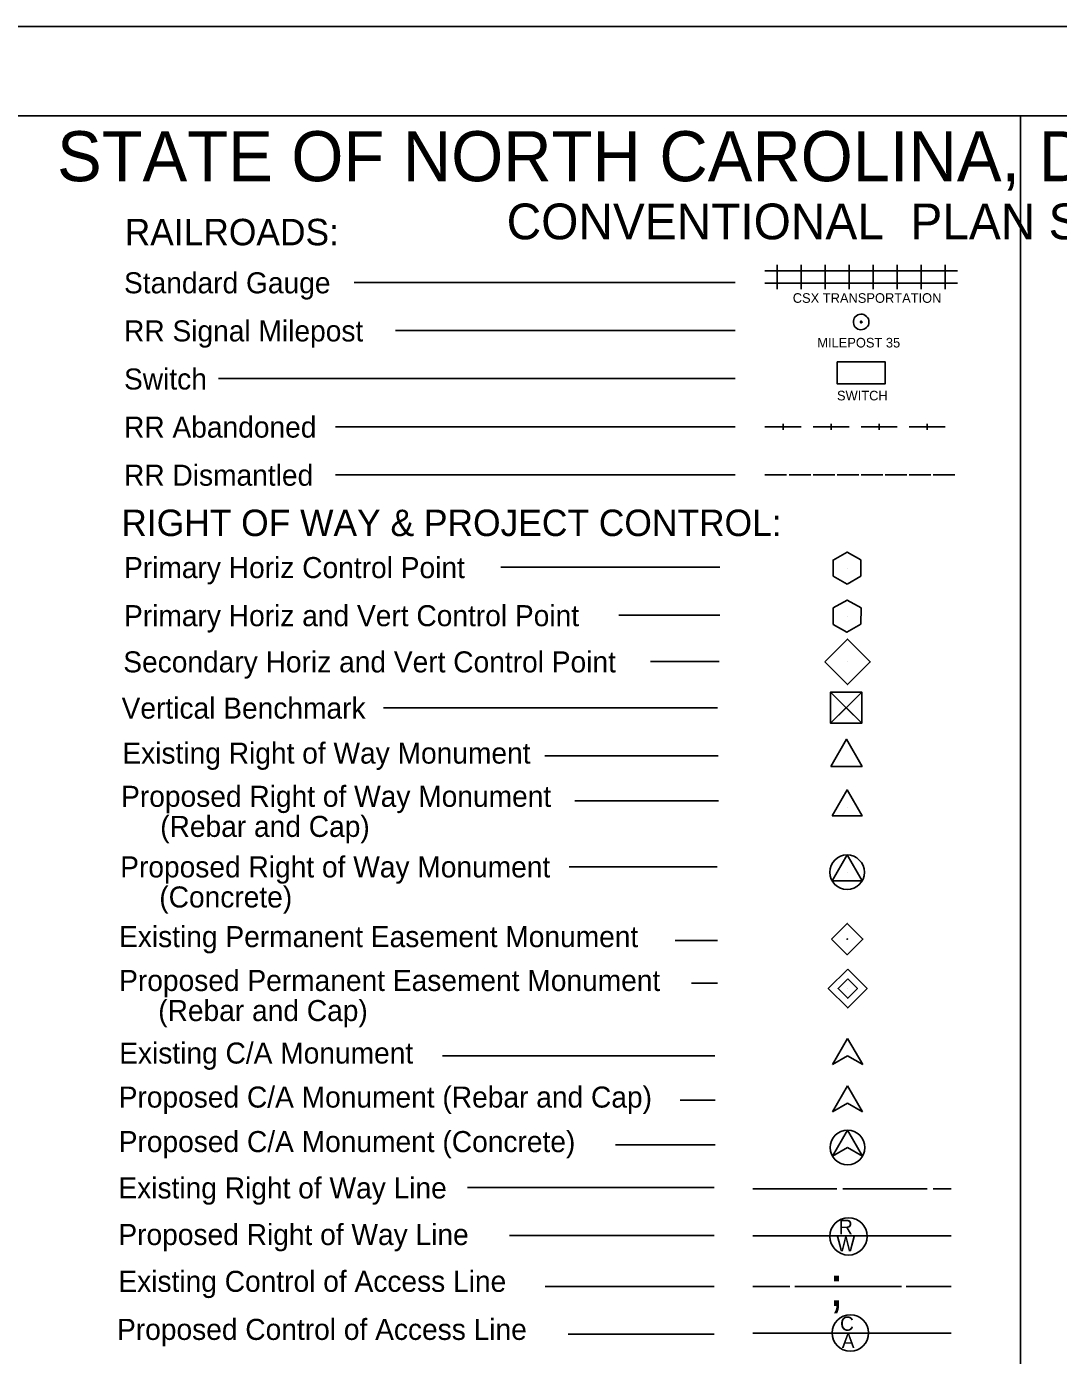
# Model space of a CAD drawing. Extents: x 0 to 3, y 0 to 1.83.
# Drawn here: x 0.722 to 1.443, y 0.904 to 1.833 of the extents above; entities that cross this region are included whole.
import ezdxf

# ---------------------------------------------------------------- set-up
doc = ezdxf.new("R2010")
doc.units = 0
for name, color, linetype in [('P_RDY_ROW_Permanent_Easement', 7, 'Continuous'), ('Sheet_Plan', 7, 'Continuous'), ('Sheet_Symbology', 7, 'Continuous'), ('z - Construction', 7, 'Continuous')]:
    doc.layers.add(name, color=color, linetype=linetype)

msp = doc.modelspace()

# ---------------------------------------------------------------- linework, layer by layer
at = {"layer": 'P_RDY_ROW_Permanent_Easement'}
msp.add_line((1.2958, 1.16066), (1.2958, 1.16066), dxfattribs=at)
for points in [[(1.2958, 1.1742), (1.30934, 1.16066), (1.2958, 1.14712), (1.28226, 1.16066)], [(1.2958, 1.16743), (1.30257, 1.16066), (1.2958, 1.15389), (1.28903, 1.16066)]]:
    msp.add_lwpolyline(points, close=True, dxfattribs=at)
at = {"layer": 'Sheet_Plan'}
msp.add_line((2.77083, 1.77083), (0.06249, 1.77083), dxfattribs=at)
at = {"layer": 'Sheet_Symbology'}
for p, q in [((1.24637, 1.64982), (1.24637, 1.66664)), ((1.26318, 1.64982), (1.26318, 1.66664)), ((1.28, 1.64982), (1.28, 1.66664)), ((1.29681, 1.64982), (1.29681, 1.66664)), ((1.31363, 1.64982), (1.31363, 1.66664)), ((1.33044, 1.64982), (1.33044, 1.66664)), ((1.34726, 1.64982), (1.34726, 1.66664)), ((1.36408, 1.64982), (1.36408, 1.66664)), ((1.21712, 1.65442), (0.95074, 1.65442)), ((1.23796, 1.66243), (1.25477, 1.66243)), ((1.23796, 1.65402), (1.25477, 1.65402)), ((1.25477, 1.66243), (1.27159, 1.66243)), ((1.25477, 1.65402), (1.27159, 1.65402)), ((1.27159, 1.66243), (1.28841, 1.66243)), ((1.27159, 1.65402), (1.28841, 1.65402)), ((1.28841, 1.66243), (1.30522, 1.66243)), ((1.28841, 1.65402), (1.30522, 1.65402)), ((1.30522, 1.66243), (1.32204, 1.66243)), ((1.30522, 1.65402), (1.32204, 1.65402)), ((1.32204, 1.66243), (1.33885, 1.66243)), ((1.32204, 1.65402), (1.33885, 1.65402)), ((1.33885, 1.66243), (1.35567, 1.66243)), ((1.33885, 1.65402), (1.35567, 1.65402)), ((1.35567, 1.66243), (1.37248, 1.66243)), ((1.35567, 1.65402), (1.37248, 1.65402)), ((1.21712, 1.62079), (0.97956, 1.62079)), ((1.21712, 1.58716), (0.85573, 1.58716)), ((1.21712, 1.55353), (0.93771, 1.55353)), ((1.23796, 1.55353), (1.26318, 1.55353)), ((1.25057, 1.55563), (1.25057, 1.55143)), ((1.27159, 1.55353), (1.29681, 1.55353)), ((1.2842, 1.55563), (1.2842, 1.55143)), ((1.30522, 1.55353), (1.33044, 1.55353)), ((1.31783, 1.55563), (1.31783, 1.55143)), ((1.33885, 1.55353), (1.36408, 1.55353)), ((1.35146, 1.55563), (1.35146, 1.55143)), ((1.21712, 1.5199), (0.93771, 1.5199)), ((1.21712, 1.5199), (0.93771, 1.5199)), ((1.23796, 1.5199), (1.25309, 1.5199)), ((1.25477, 1.5199), (1.26991, 1.5199)), ((1.27159, 1.5199), (1.28672, 1.5199)), ((1.28841, 1.5199), (1.30354, 1.5199)), ((1.30522, 1.5199), (1.32035, 1.5199)), ((1.32204, 1.5199), (1.33717, 1.5199)), ((1.33885, 1.5199), (1.35399, 1.5199)), ((1.35567, 1.5199), (1.3708, 1.5199)), ((1.20634, 1.45534), (1.05327, 1.45534)), ((1.29535, 1.45472), (1.29535, 1.45472)), ((1.20634, 1.42171), (1.13585, 1.42171)), ((1.29533, 1.42114), (1.29533, 1.42114)), ((1.20582, 1.38941), (1.1578, 1.38941)), ((1.29556, 1.38906), (1.29556, 1.38906)), ((1.20466, 1.35709), (0.97119, 1.35709)), ((1.29472, 1.35711), (1.29472, 1.35711)), ((1.20518, 1.32349), (1.08402, 1.32349)), ((1.20535, 1.29191), (1.10491, 1.29191)), ((1.29534, 1.28751), (1.29534, 1.28751)), ((1.20451, 1.24583), (1.10111, 1.24583)), ((1.29537, 1.242), (1.29537, 1.242)), ((1.20464, 1.19421), (1.17512, 1.19421)), ((1.2955, 1.19531), (1.2955, 1.19531)), ((1.20464, 1.16458), (1.18647, 1.16458)), ((1.28526, 1.10757), (1.29577, 1.12573)), ((1.29577, 1.12573), (1.30628, 1.10757)), ((1.20297, 1.11377), (1.01255, 1.11377)), ((1.29577, 1.11362), (1.28526, 1.10757)), ((1.30628, 1.10757), (1.29577, 1.11362)), ((1.28521, 1.07459), (1.29572, 1.09275)), ((1.29572, 1.09275), (1.30623, 1.07459)), ((1.20313, 1.0826), (1.17864, 1.0826)), ((1.29572, 1.08064), (1.28521, 1.07459)), ((1.30623, 1.07459), (1.29572, 1.08064)), ((1.28521, 1.04347), (1.29572, 1.06163)), ((1.29572, 1.06163), (1.30623, 1.04347)), ((1.20313, 1.05148), (1.13353, 1.05148)), ((1.29572, 1.04952), (1.28521, 1.04347)), ((1.30623, 1.04347), (1.29572, 1.04952)), ((1.2024, 1.02159), (1.03001, 1.02159)), ((1.22935, 1.02062), (1.28821, 1.02062)), ((1.29241, 1.02062), (1.35127, 1.02062)), ((1.35547, 1.02062), (1.36808, 1.02062)), ((1.2024, 0.98795), (1.05939, 0.98795)), ((1.22935, 0.98774), (1.36808, 0.98774)), ((1.2024, 0.95243), (1.08428, 0.95243)), ((1.22935, 0.95243), (1.25535, 0.95243)), ((1.25872, 0.95243), (1.3334, 0.95243)), ((1.33676, 0.95243), (1.36808, 0.95243)), ((1.2024, 0.91911), (1.1003, 0.91911)), ((1.22935, 0.91975), (1.36808, 0.91975))]:
    msp.add_line(p, q, dxfattribs=at)
for points in [[(1.3107, 1.62678), (1.31059, 1.62787), (1.31027, 1.62896), (1.30972, 1.62995), (1.30896, 1.63071), (1.30808, 1.63137), (1.3071, 1.63191), (1.30612, 1.63213), (1.30491, 1.63224), (1.30382, 1.63202), (1.30284, 1.63169), (1.30186, 1.63115), (1.30109, 1.63038), (1.30044, 1.6294), (1.3, 1.62842), (1.29978, 1.62733), (1.29978, 1.62623), (1.3, 1.62514), (1.30044, 1.62416), (1.30109, 1.62317), (1.30186, 1.62241), (1.30284, 1.62186), (1.30382, 1.62154), (1.30491, 1.62132), (1.30612, 1.62143), (1.3071, 1.62165), (1.30808, 1.62219), (1.30896, 1.62284), (1.30972, 1.62361), (1.31027, 1.6246), (1.31059, 1.62569), (1.3107, 1.62678)], [(1.30546, 1.62743), (1.30513, 1.62743), (1.3048, 1.62722), (1.30459, 1.62689), (1.3047, 1.62656), (1.30491, 1.62623), (1.30524, 1.62612), (1.30557, 1.62623), (1.30579, 1.62645), (1.3059, 1.62689), (1.30579, 1.62722), (1.30546, 1.62743)], [(1.29535, 1.44353), (1.2856, 1.44906), (1.2856, 1.46025), (1.29535, 1.4659), (1.3051, 1.46037), (1.3051, 1.44906), (1.29535, 1.44353)], [(1.30561, 1.368), (1.2838, 1.34619), (1.2947, 1.3571), (1.30561, 1.34619), (1.2838, 1.368)], [(1.2947, 1.3571), (1.30561, 1.368), (1.2838, 1.368), (1.2947, 1.3571)], [(1.2947, 1.3571), (1.2838, 1.34619), (1.30561, 1.34619), (1.2947, 1.3571)], [(1.28397, 1.31599), (1.29489, 1.33496), (1.30582, 1.31599), (1.28397, 1.31599)]]:
    msp.add_lwpolyline(points, dxfattribs=at)
for points in [[(1.28841, 1.59887), (1.32204, 1.59887), (1.32204, 1.58357), (1.28841, 1.58357)], [(1.28553, 1.42682), (1.29539, 1.43232), (1.30525, 1.42689), (1.3051, 1.41559), (1.29524, 1.40986), (1.28553, 1.41536)], [(1.27974, 1.38912), (1.29564, 1.40502), (1.31158, 1.38909), (1.29567, 1.37319)], [(1.2838, 1.368), (1.30561, 1.368), (1.30561, 1.34619), (1.2838, 1.34619)], [(1.28483, 1.28145), (1.29534, 1.29962), (1.30585, 1.28145)], [(1.28486, 1.23595), (1.29537, 1.25411), (1.30588, 1.23595)], [(1.28458, 1.19531), (1.2955, 1.20624), (1.30642, 1.19531), (1.2955, 1.18439)]]:
    msp.add_lwpolyline(points, close=True, dxfattribs=at)
for centre, radius in [((1.29537, 1.242), 0.01211), ((1.2955, 1.19531), 0.000212), ((1.29572, 1.04952), 0.01211), ((1.29637, 0.9874), 0.01304), ((1.2977, 0.91992), 0.01275)]:
    msp.add_circle(centre, radius, dxfattribs=at)
at = {"layer": 'z - Construction'}
for p, q in [((2.83333, 1.83333), (0, 1.83333)), ((1.41666, 1.77083), (1.41662, 0.0625))]:
    msp.add_line(p, q, dxfattribs=at)

# ---------------------------------------------------------------- texts
at = {"layer": 'Sheet_Symbology'}
for s, height, p in [('STATE OF NORTH CAROLINA, DIVISION OF HIGHWAYS', 0.035, (0.7429, 1.72519)), ('CONVENTIONAL  PLAN SHEET SYMBOLS', 0.025, (1.05732, 1.68458)), ('RAILROADS:', 0.018497, (0.79019, 1.6804)), ('Standard Gauge', 0.0147137, (0.78973, 1.64681)), ('CSX TRANSPORTATION', 0.0067262, (1.2574, 1.64017)), ('RR Signal Milepost', 0.0147137, (0.78973, 1.61318)), ('MILEPOST 35', 0.0067262, (1.27453, 1.60894)), ('Switch', 0.014714, (0.78973, 1.57955)), ('SWITCH', 0.006726, (1.28832, 1.57194)), ('RR Abandoned', 0.0147137, (0.78973, 1.54592)), ('RR Dismantled', 0.0147137, (0.78973, 1.51229)), ('RIGHT OF WAY & PROJECT CONTROL:', 0.0184972, (0.78783, 1.47709)), ('Primary Horiz Control Point', 0.0147137, (0.78974, 1.44769)), ('Primary Horiz and Vert Control Point', 0.0147137, (0.78974, 1.41406)), ('Secondary Horiz and Vert Control Point', 0.0147137, (0.78921, 1.38176)), ('Vertical Benchmark', 0.0147137, (0.78805, 1.34944)), ('Existing Right of Way Monument', 0.0147137, (0.78858, 1.31798)), ('Proposed Right of Way Monument', 0.0147137, (0.7877, 1.28775)), ('     (Rebar and Cap)', 0.0147137, (0.7877, 1.26673)), ('Proposed Right of Way Monument', 0.0147137, (0.78707, 1.2384)), ('     (Concrete)', 0.0147137, (0.78707, 1.21738)), ('Existing Permanent Easement Monument', 0.0147137, (0.78626, 1.18965)), ('Proposed Permanent Easement Monument', 0.0147137, (0.78632, 1.15899)), ('     (Rebar and Cap)', 0.0147137, (0.78632, 1.13797)), ('Existing C/A Monument', 0.0147137, (0.78636, 1.10825)), ('Proposed C/A Monument (Rebar and Cap)', 0.0147137, (0.78601, 1.07747)), ('Proposed C/A Monument (Concrete)', 0.0147137, (0.78601, 1.04635)), ('Existing Right of Way Line', 0.0147137, (0.78579, 1.01393)), ('Proposed Right of Way Line', 0.0147137, (0.78579, 0.98135)), ('R', 0.01022, (1.28953, 0.98893)), ('W', 0.01022, (1.28807, 0.9769)), ('Existing Control of Access Line', 0.0147137, (0.78579, 0.94863)), (';', 0.02775, (1.28281, 0.93867)), ('Proposed Control of Access Line', 0.0147137, (0.78487, 0.91502)), ('C', 0.00999, (1.29049, 0.92143)), ('A', 0.00999, (1.29168, 0.90943))]:
    msp.add_text(s, height=height, dxfattribs=at).set_placement(p)

doc.saveas('drawing.dxf')
